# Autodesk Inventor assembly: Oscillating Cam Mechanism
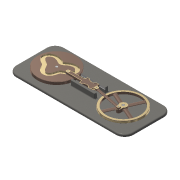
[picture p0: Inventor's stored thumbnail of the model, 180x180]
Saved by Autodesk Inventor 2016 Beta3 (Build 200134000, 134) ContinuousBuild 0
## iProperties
Created: 2016-02
Part Number: Oscillating Cam Mechanism
Document SubType Name: Assembly
Designer: User
Author: User
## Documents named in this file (11)
- D:\My Data\Books_Final Books\Autodesk Inventor 2015_resources\Chapter 7\oscillating-cam-mechanism\Oscillating Cam Mechanism.iam
- D:\My Data\Books_Final Books\Autodesk Inventor 2015_resources\Chapter 7\oscillating-cam-mechanism\Base Plate.ipt
- D:\My Data\Books_Final Books\Autodesk Inventor 2015_resources\Chapter 7\oscillating-cam-mechanism\Bearing.ipt
- D:\My Data\Books_Final Books\Autodesk Inventor 2015_resources\Chapter 7\oscillating-cam-mechanism\Tappet.ipt
- D:\My Data\Books_Final Books\Autodesk Inventor 2015_resources\Chapter 7\oscillating-cam-mechanism\Pin 12x26.ipt
- D:\My Data\Books_Final Books\Autodesk Inventor 2015_resources\Chapter 7\oscillating-cam-mechanism\Pin 5x13.ipt
- D:\My Data\Books_Final Books\Autodesk Inventor 2015_resources\Chapter 7\oscillating-cam-mechanism\Oscillating Wheel.ipt
- D:\My Data\Books_Final Books\Autodesk Inventor 2015_resources\Chapter 7\oscillating-cam-mechanism\Lever.ipt
- D:\My Data\Books_Final Books\Autodesk Inventor 2015_resources\Chapter 7\oscillating-cam-mechanism\Pin 5x8.ipt
- D:\My Data\Books_Final Books\Autodesk Inventor 2015_resources\Chapter 7\oscillating-cam-mechanism\Pin 5x22.ipt
- D:\My Data\Books_Final Books\Autodesk Inventor 2015_resources\Chapter 7\oscillating-cam-mechanism\Cam_1.ipt
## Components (11 placed, 10 different names)
1. Base Plate:1 — Mate:1, Flush:1, Insert:6, Insert:12
2. Bearing:1 — Insert:3, Insert:4, Transitional:1
3. Tappet:1 — Insert:4, Mate:1, Flush:1, Insert:7, Insert:9
4. Oscillating Wheel:1 — Insert:6, Mate:2, Insert:8
5. Lever:1 — Insert:7, Mate:2, Insert:10
6. Pin 5x13:1 — Insert:3
7. Pin 12x26:1 — Insert:11, Insert:12
8. Pin 12x26:2 — Insert:8
9. Pin 5x8:1 — Insert:9
10. Pin 5x22:1 — Insert:10
11. Disc Cam:1 — Insert:11, Transitional:1
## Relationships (13: Insert 9, Mate 2, Flush 1, Transitional 1)
- Insert:3: Bearing:1 ↔ Pin 5x13:1
- Insert:4: Bearing:1 ↔ Tappet:1
- Mate:1: Base Plate:1 ↔ Tappet:1
- Flush:1: Base Plate:1 ↔ Tappet:1
- Insert:6: Base Plate:1 ↔ Oscillating Wheel:1
- Insert:7: Tappet:1 ↔ Lever:1
- Mate:2: Oscillating Wheel:1 ↔ Lever:1
- Insert:8: Oscillating Wheel:1 ↔ Pin 12x26:2
- Insert:9: Tappet:1 ↔ Pin 5x8:1
- Insert:10: Lever:1 ↔ Pin 5x22:1
- Insert:11: Pin 12x26:1 ↔ Disc Cam:1
- Insert:12: Base Plate:1 ↔ Pin 12x26:1
- Transitional:1: Bearing:1 ↔ Disc Cam:1
